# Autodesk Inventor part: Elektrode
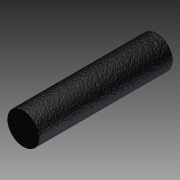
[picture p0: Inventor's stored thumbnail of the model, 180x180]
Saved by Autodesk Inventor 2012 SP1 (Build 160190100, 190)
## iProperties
Created: 2012-10
Part Number: Elektrode
Material: Default
Document SubType Name: Modeling
Designer: Dominic Mähling
Density: 1 g/cm^3
Author: Dominic Mähling
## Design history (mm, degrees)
derived "Funkenstrecke master.ipt"
feature "Elektrode::Funkenstrecke master.ipt" dims "d0" = 10
tag "Bezeichnung1"
node "Volumenkörper1"
